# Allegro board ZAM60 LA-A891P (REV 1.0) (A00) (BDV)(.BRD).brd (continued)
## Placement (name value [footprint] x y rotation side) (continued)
LA6  BLM15PX330SN1D_2P  [MURAT_BLM15PX330SN1D_2P]  23.09 7.09 180 bottom
LA7  BLM15PX330SN1D_2P  [MURAT_BLM15PX330SN1D_2P]  23.09 8.8 180 bottom
LA8  BLM15PX330SN1D_2P  [MURAT_BLM15PX330SN1D_2P]  23.09 10.01 180 bottom
LA9  BLM15PX330SN1D_2P  [MURAT_BLM15PX330SN1D_2P]  23.09 11.72 180 bottom
LA10  BLM15PX330SN1D_2P  [MURAT_BLM15PX330SN1D_2P]  27.65 18.57 270 top
LA11  BLM15PX330SN1D_2P  [MURAT_BLM15PX330SN1D_2P]  24.2 18.62 270 top
LC1  2.2UH_LQM2MPN2R2NG0L_30%  [MURAT_LQM2MPN2R2NG0L_2P]  160.72 81.48 270 top
LC2  2.2UH_LQM2MPN2R2NG0L_30%  [MURAT_LQM2MPN2R2NG0L_2P]  163.07 81.48 270 top
LC3  2.2UH_LQM2MPN2R2NG0L_30%  [MURAT_LQM2MPN2R2NG0L_2P]  173.76 82.79 180 bottom
LC4  2.2UH_LQM2MPN2R2NG0L_30%  [MURAT_LQM2MPN2R2NG0L_2P]  142.75 81.28 90 bottom
LC5  2.2UH_LQM2MPN2R2NG0L_30%  [MURAT_LQM2MPN2R2NG0L_2P]  145.03 81.28 90 bottom
LED3  LTW-193ZDS5_WHITE  [LED_LTW-193ZDS5_2P]  295.45 87.55 0 top
LI1  DLW21HN900HQ2L_4P  [MURAT_DLW21HN900HQ2L_4P]  86 89 90 top
LI2  DLW21HN900HQ2L_4P  [MURAT_DLW21HN900HQ2L_4P]  87.6 88.99 90 top
LI3  DLW21HN900HQ2L_4P  [MURAT_DLW21HN900HQ2L_4P]  83.28 92.39 180 top
LI4  DLW21HN900HQ2L_4P  [MURAT_DLW21HN900HQ2L_4P]  242.97 86.69 90 bottom
LI5  DLW21HN900HQ2L_4P  [MURAT_DLW21HN900HQ2L_4P]  281.65 59.14 0 bottom
LI6  DLW21HN900HQ2L_4P  [MURAT_DLW21HN900HQ2L_4P]  281.65 60.8 0 bottom
LI7  DLW21HN900HQ2L_4P  [MURAT_DLW21HN900HQ2L_4P]  279.49 56.29 0 bottom
LI8  DLW21HN900HQ2L_4P  [MURAT_DLW21HN900HQ2L_4P]  239.78 88.54 90 bottom
LI9  DLW21HN900HQ2L_4P  [MURAT_DLW21HN900HQ2L_4P]  238.13 88.54 90 bottom
LL1  4.7UH_BRC2012T4R7MD_20%  [TAIYO_BRC2012T4R7MD_2P]  250.95 85.99 270 bottom
LV1  BLM15BB221SN1D_2P~D  [MURAT_BLM15BB221SN1D_2P]  115.25 86.96 270 top
LV3  DLW21HN900HQ2L_4P  [MURAT_DLW21HN900HQ2L_4P]  210.95 93.52 90 bottom
LV6  DLW21HN900HQ2L_4P  [MURAT_DLW21HN900HQ2L_4P]  208.85 93.52 90 bottom
LV10  DLW21HN900HQ2L_4P  [MURAT_DLW21HN900HQ2L_4P]  206.76 93.52 90 bottom
LV12  DLW21HN900HQ2L_4P  [MURAT_DLW21HN900HQ2L_4P]  213.05 93.52 90 bottom
LV22  BLM15PX181SN1D_2P  [MURAT_BLM15PX181SN1D_2P]  207.62 69.45 180 bottom
LV23  BLM15PX181SN1D_2P  [MURAT_BLM15PX181SN1D_2P]  209.61 70.72 90 bottom
LV24  BLM15PX181SN1D_2P  [MURAT_BLM15PX181SN1D_2P]  213.85 80.25 180 bottom
LV25  BLM15PX181SN1D_2P  [MURAT_BLM15PX181SN1D_2P]  213.1 75.93 0 bottom
LV27  DLW21HN900HQ2L_4P  [MURAT_DLW21HN900HQ2L_4P]  96.12 95.57 270 bottom
LZ1  DLW21HN900HQ2L_4P  [MURAT_DLW21HN900HQ2L_4P]  107.69 81.27 180 bottom
MIC1  SPM1437HM4H-6_6P  [KNOW_SPM1437HM4H-6_6P]  228.81 99.88 0 top
NOREF  -  []  169.65 73.51 0 top
NOREF#2  -  []  236.8 8.1 180 top
NOREF#3  -  []  135.19 -34.6 0 top
NOREF#4  -  []  88.07 31.21 0 top
NOREF#5  -  []  166.94 24.23 0 top
NOREF#6  -  []  56.7 105.85 270 top
NOREF#7  -  []  207.77 12.8 0 top
NOREF#8  -  []  69.98 61.55 90 top
NOREF#9  -  []  230.2 105.85 0 top
NOREF#10  -  []  92.2 88.9 0 top
NOREF#11  -  []  118.23 38.84 0 top
NOREF#12  -  []  277.87 63.56 0 top
NOREF#13  -  []  118.7 105.85 0 top
NOREF#14  -  []  299.7 11.15 270 top
NOREF#15  -  []  135.67 82 0 top
NOREF#16  -  []  266.87 24.6 0 top
NOREF#17  -  []  291.3 90.65 0 top
NOREF#18  -  []  163.57 33.84 0 top
NOREF#19  -  []  119.11 148.18 0 top
NOREF#20  -  []  283.7 49.65 270 top
NOREF#21  -  []  151.7 15.65 0 top
NOREF#22  -  []  184.7 105.85 0 top
NOREF#23  -  []  240.35 43.65 270 top
NOREF#24  -  []  274.91 67.86 180 bottom
NOREF#25  -  []  274.39 60.17 180 bottom
NOREF#26  -  []  258.95 72.21 180 bottom
NOREF#27  -  []  169.85 18.78 180 bottom
NOREF#28  -  []  193.94 28.42 180 bottom
PBATT1  DEREN_40-42251-01001RHF  [DEREN_40-42251-01001RHF_10P-T]  60.7 16.65 180 bottom
PC1  1U_0603_10V4Z  [C_0603]  291.96 7.03 270 top
PC3  2200P_0402_50V7K  [C_0402]  63.24 12.39 0 top
PC4  1500P_0402_50V7K  [C_0402]  48.31 11.79 0 top
PC5  0.022U_0805_50V7K  [C_0805]  63.18 103.76 270 top
PC9  1000P_0603_50V7K  [C_0603]  62.16 105.94 90 bottom
PC10  10U_0805_25V6K  [C_0805]  63.23 91.48 270 bottom
PC20  0.1U_0402_25V6  [C_0402]  74.28 101.36 270 top
PC21  10U_0805_25V6K  [C_0805]  59.32 101.52 0 top
PC22  10U_0805_25V6K  [C_0805]  63.64 105.93 90 bottom
PC100  4.7U_0603_10V6K  [C_0603]  218.3 48.37 270 bottom
PC101  10U_0805_25V6K  [C_0805]  218.23 57.86 270 bottom
PC102  10U_0805_25V6K  [C_0805]  217.79 57.86 270 top
PC105  2200P_0402_50V7K  [C_0402]  219.58 57.52 270 top
PC106  0.1U_0402_25V6  [C_0402]  219.58 57.51 270 bottom
PC109  0.1U_0603_25V7K  [C_0603]  221.98 49.32 0 top
PC110  0.1U_0603_25V7K  [C_0603]  213.34 49.32 0 top
PC111  680P_0603_50V7K  [C_0603]  227.01 57.63 90 top
PC113  220U_6.3V_M  [C_APXK6R3ARA221MF451]  228.53 49.51 180 bottom
PC114  680P_0603_50V7K  [C_0603]  210.17 55.04 270 top
PC115  220U_6.3V_M  [C_APXK6R3ARA221MF451]  207.72 49.57 0 bottom
PC117  0.1U_0603_25V7K  [C_0603]  219.44 51.42 90 bottom
PC118  4.7U_0603_10V6K  [C_0603]  218.17 51.42 90 bottom
PC119  1U_0603_10V6K  [C_0603]  214.87 47.1 180 top
PC200  10U_0805_25V6K  [C_0805]  63.18 23.68 270 top
PC201  10U_0805_25V6K  [C_0805]  64.89 23.68 270 top
PC203  2200P_0402_50V7K  [C_0402]  62.1 22.85 270 bottom
PC204  0.22U_0603_16V7K  [C_0603]  65.97 15.66 270 bottom
PC205  22U_0805_6.3V6M  [C_0805]  70.63 12.11 0 bottom
PC206  0.1U_0402_25V6  [C_0402]  61.2 22.85 270 bottom
PC207  220U_D2_2VY_R17M  [C_D2]  70.89 26.52 180 bottom
PC208  680P_0603_50V7K  [C_0603]  63.56 16.61 90 top
PC209  1U_0603_10V6K  [C_0603]  64.07 11.09 270 top
PC211  1U_0603_10V6K  [C_0603]  65.53 7.28 0 top
PC212  0.033U_0402_16V7K  [C_0402]  71.03 10.71 0 bottom
PC213  100P_0402_50V8J  [C_0402]  71.04 8.03 90 bottom
PC214  .1U_0402_16V7K  [C_0402]  71.03 9.82 0 bottom
PC215  .1U_0402_16V7K  [C_0402]  69.61 8.1 180 top
PC300  2200P_0402_50V7K  [C_0402]  201.67 63.8 180 bottom
PC301  680P_0603_50V7K  [C_0603]  201.72 58.66 180 top
PC302  0.1U_0603_25V7K  [C_0603]  205.15 62.59 180 top
PC303  10U_0805_25V6K  [C_0805]  200.76 61.68 270 bottom
PC304  330P_0402_50V7K  [C_0402]  207.62 59.54 180 bottom
PC305  47U_0805_6.3V6M  [C_0805]  204.3 50.72 0 top
PC306  47U_0805_6.3V6M  [C_0805]  204.3 52.43 0 top
PC307  22U_0805_6.3VAM  [C_0805]  201.11 50.72 180 top
PC308  22U_0805_6.3VAM  [C_0805]  201.11 52.43 180 top
PC309  4.7U_0603_6.3V6K  [C_0603]  206.68 62.85 0 bottom
PC310  4.7U_0603_6.3V6K  [C_0603]  204.33 63.93 0 bottom
PC311  0.1U_0402_25V6  [C_0402]  201.29 62.83 180 bottom
PC400  1U_0402_6.3V6K  [C_0402]  115.6 74.02 0 bottom
PC401  4.7U_0805_6.3V6K  [C_0805]  113.75 76.94 180 bottom
PC402  .1U_0402_16V7K  [C_0402]  116.53 72.16 270 bottom
PC403  0.01U_0402_25V7K  [C_0402]  106.28 74.1 270 bottom
PC404  22U_0805_6.3V6M  [C_0805]  109 76.94 0 bottom
PC500  4700P_0603_50V7K  [C_0603]  104.63 61.7 90 bottom
PC501  .1U_0402_16V7K  [C_0402]  105.71 63.05 270 bottom
PC502  0.068U_0402_16V7K  [C_0402]  108.7 66.03 270 top
PC503  1000P_0402_50V7K  [C_0402]  97.44 55.73 0 bottom
PC504  0.1U_0402_25V6  [C_0402]  97.7 58.15 0 bottom
PC505  1U_0603_10V6K  [C_0603]  98.74 69.76 0 top
PC506  100P_0402_50V8J  [C_0402]  109.53 69.77 180 top
PC507  0.33U_0603_10V7K  [C_0603]  106.54 72.56 270 top
PC508  680P_0603_50V7K  [C_0603]  102.28 50.08 90 bottom
PC509  1U_0603_10V7K  [C_0603]  105.39 56.94 90 bottom
PC510  1U_0603_10V7K  [C_0603]  105.27 72.56 270 top
PC511  0.1U_0402_25V6  [C_0402]  98.92 71.75 270 top
PC512  1500P_0402_50V7K  [C_0402]  108.63 72.45 270 top
PC513  0.068U_0402_16V7K  [C_0402]  109.58 66.03 270 top
PC514  47P_0402_50V8J  [C_0402]  102.07 72.61 0 top
PC515  10U_0805_25V6K  [C_0805]  99.35 52.17 0 top
PC516  10U_0805_25V6K  [C_0805]  99.35 52.17 0 bottom
PC517  10U_0805_25V6K  [C_0805]  99.35 50.39 0 bottom
PC518  10U_0805_25V6K  [C_0805]  99.35 50.39 0 top
PC519  100U_D_20VM_R55M  [C_D]  97.14 46.91 0 bottom
PC520  2200P_0402_50V7K  [C_0402]  99.74 53.57 0 top
PC521  0.1U_0402_25V6  [C_0402]  99.67 54.5 0 top
PC700  0.1U_0603_25V7K  [C_0603]  68.64 93.13 270 bottom
PC701  1U_0603_25V6K  [C_0603]  78.48 84.62 90 top
PC702  0.1U_0402_25V6  [C_0402]  79.27 88.77 180 bottom
PC703  0.1U_0402_25V6  [C_0402]  77.4 85.78 270 top
PC704  10U_0805_25V6K  [C_0805]  83.55 66.81 270 top
PC705  10U_0805_25V6K  [C_0805]  85.26 66.81 270 top
PC706  10U_0805_25V6K  [C_0805]  81.84 66.81 270 top
PC707  10U_0805_25V6K  [C_0805]  86.73 64.87 180 bottom
PC708  22U_0805_25V6M  [C_0805]  86.73 63.12 180 bottom
PC709  10U_0805_25V6K  [C_0805]  77.05 88.54 90 bottom
PC710  1U_0603_10V6K  [C_0603]  74.67 81.38 180 bottom
PC711  0.1U_0402_25V6  [C_0402]  79.56 85.78 270 top
PC712  0.047U_0603_25V7K~D  [C_0603]  73.2 83.87 0 bottom
PC713  2200P_0402_50V7K  [C_0402]  69.9 66.57 0 top
PC714  22U_0805_25V6M  [C_0805]  69.03 69.76 0 top
PC715  22U_0805_25V6M  [C_0805]  69.02 69.76 0 bottom
PC716  22U_0805_25V6M  [C_0805]  68.97 68.01 0 top
PC717  22U_0805_25V6M  [C_0805]  69.05 68.02 0 bottom
PC718  100P_0402_50V8J  [C_0402]  81.34 84.86 90 top
PC719  100P_0402_50V8J  [C_0402]  82.23 84.29 90 top
PC721  1000P_0603_50V7K  [C_0603]  74.06 78.29 270 top
PC722  0.1U_0603_25V7K  [C_0603]  90.28 63.74 270 top
PC723  10U_0805_25V6K  [C_0805]  88.57 63.89 270 top
PC724  10U_0805_25V6K  [C_0805]  90.28 63.89 270 bottom
PC725  10U_0805_25V6K  [C_0805]  88.57 63.89 270 bottom
PC726  0.1U_0402_25V6  [C_0402]  78.99 81.9 270 top
PC727  0.1U_0402_25V6  [C_0402]  78.98 80.11 0 top
PC728  0.1U_0402_25V6  [C_0402]  79.88 80.99 90 top
PC729  1U_0603_25V6K  [C_0603]  81.91 80.94 90 top
PC732  0.1U_0402_25V6  [C_0402]  69.31 66.62 0 bottom
PC737  100P_0402_50V8J  [C_0402]  84.07 81.05 90 bottom
PC741  100P_0402_50V8J  [C_0402]  84.07 79.21 90 bottom
PC805  0.1U_0402_10V7K  [C_0402]  66.46 32.81 0 top
PC807  0.47U_0805_25V6K  [C_0805]  116.61 100.82 0 top
PC809  1500P_0402_50V7K  [C_0402]  63.57 39.47 180 bottom
PC810  0.1U_0402_10V7K  [C_0402]  44.43 17.56 90 top
PC813  0.1U_0603_50V4Z  [C_0603]  80.88 39.73 90 top
PC815  0.1U_0603_25V7K  [C_0603]  79.61 39.73 90 top
PC816  0.047U_0603_25V7M  [C_0603]  73.9 36.75 180 top
PC817  0.1U_0402_25V4Z~D  [C_0402]  73.91 35.67 180 top
PC900  22U_0805_6.3V6M  [C_0805]  123.55 57.86 90 bottom
PC901  22U_0805_6.3V6M  [C_0805]  124.58 64.4 90 bottom
PC902  22U_0805_6.3V6M  [C_0805]  123.62 67.49 90 bottom
PC903  22U_0805_6.3V6M  [C_0805]  124.58 60.92 90 bottom
PC904  22U_0805_6.3V6M  [C_0805]  121.74 60.92 90 bottom
PC913  22U_0805_6.3V6M  [C_0805]  120.71 57.77 90 bottom
PC914  22U_0805_6.3V6M  [C_0805]  121.74 64.32 90 bottom
PC915  2.2U_0805_10V6K  [C_0805]  120.77 67.49 90 bottom
PC916  2.2U_0805_10V6K  [C_0805]  118.95 64.29 90 bottom
PC917  22U_0805_6.3V6M  [C_0805]  118.95 60.87 90 bottom
PC966  220U 2.5V Y D2 ESR9M H1.9 SX  [C_D2]  115.19 57.19 180 bottom
PD1  -  [TVNST52302AB0_SOT523-3]  54.8 10.26 180 top
PD2  -  [TVNST52302AB0_SOT523-3]  52.7 10.26 180 top
PD3  BAS40CW SOT-323  [BAS40-05W_SC70-3]  292.62 8.05 90 top
PD4  SDMK0340L-7-F_SOD323-2~D  [RB751V-40_SOD323-2]  50.73 9.36 270 top
PD5  -  [AZC199-02SPR7G_SOT23-3]  64.08 106.49 90 top
PD702  SDMK0340L-7-F_SOD323-2~D  [SDMK0340L-7-F_SOD323-2]  75.05 85.51 180 top
PD704  SDMK0340L-7-F_SOD323-2~D  [SDMK0340L-7-F_SOD323-2]  75.04 87.24 180 top
PD705  SDMK0340L-7-F_SOD323-2~D  [SDMK0340L-7-F_SOD323-2]  75.05 88.94 180 top
PD800  -  [PDS5100H-13_POWERDI5-3]  90.47 67.23 0 bottom
PD808  -  [PDS5100H-13_POWERDI5-3]  118.68 97.52 0 top
PD813  SDMK0340L-7-F_SOD323-2~D  [SDMK0340L-7-F_SOD323-2]  62.72 32.88 270 bottom
PD815  -  [BAT54CW_SOT323-3]  66.72 29.04 0 top
PD817  -  [BAT54CW_SOT323-3]  60.67 30.85 0 bottom
PH500  100K_0402_1%_NCP15WF104F03RC  [R_0402]  100.49 58.97 0 bottom
PH501  10K_0402_1%_TSM0A103F34D1RZ  [R_0402]  110.74 52.12 0 top
PJP1  PAD-OPEN 1x3m  [JUMP_43X118]  53.43 92.71 180 top
PJP4  PAD-OPEN1x1m  [JUMP_43X39]  272.98 13.89 180 bottom
PJP5  PAD-OPEN1x1m  [JUMP_43X39]  273.36 11.67 180 bottom
PJP6  PAD-OPEN1x2m  [JUMP_43X79]  30.23 16.56 0 bottom
PJP7  PAD-OPEN1x1m  [JUMP_43X39]  253.65 17.73 0 top
PJP9  PAD-OPEN1X2m  [JUMP_43X79]  39.84 9.13 180 top
PJP10  PAD-OPEN1x1m  [JUMP_43X39]  44.14 10.2 180 top
PJP11  PAD-OPEN1x1m  [JUMP_43X39]  189.6 79.67 0 top
PJP12  PAD-OPEN1x1m  [JUMP_43X39]  246.36 26.64 90 top
PJP13  PAD-OPEN1x2m  [JUMP_43X79]  239.65 60.96 90 top
PJP14  PAD-OPEN1x1m  [JUMP_43X39]  263.27 66.34 180 top
PJP15  PAD-OPEN1x1m  [JUMP_43X39]  269.87 39.03 180 top
PJP16  PAD-OPEN1x1m  [JUMP_43X39]  247.08 19.01 90 top
PJP17  PAD-OPEN1x1m  [JUMP_43X39]  244.26 33.13 0 top
PJP18  PAD-OPEN1x3m  [JUMP_43X118]  191.86 46.02 180 top
PJP20  PAD-OPEN1x1m  [JUMP_43X39]  227.19 64.07 270 top
PJP21  PAD-OPEN1x3m  [JUMP_43X118]  221.55 38.1 90 top
PJP22  PAD-OPEN1x3m  [JUMP_43X118]  214.75 34.43 270 top
PJP23  PAD-OPEN1x1m  [JUMP_43X39]  157.54 58.64 90 top
PJP24  PAD-OPEN1x1m  [JUMP_43X39]  216.66 73.15 270 bottom
PJP25  PAD-OPEN1x1m  [JUMP_43X39]  216.71 78.01 90 bottom
PJP26  PAD-OPEN1x2m  [JUMP_43X79]  277.88 24.87 0 top
PJP27  PAD-OPEN1x1m  [JUMP_43X39]  218.93 78.01 90 bottom
PJP28  PAD-OPEN1x1m  [JUMP_43X39]  218.88 72.24 90 bottom
PJP29  PAD-OPEN1x1m  [JUMP_43X39]  115.17 89.19 0 top
PJP32  PAD-OPEN1x1m  [JUMP_43X39]  240.2 54.58 90 top
PJP35  PAD-OPEN1x1m  [JUMP_43X39]  165.61 80.92 270 top
PJP36  PAD-OPEN1x3m  [JUMP_43X118]  169.45 82.12 270 top
PJP100  PAD-OPEN 1x3m  [JUMP_43X118]  214.76 62.91 0 bottom
PJP101  PAD-OPEN 1x3m  [JUMP_43X118]  208.26 45.36 270 top
PJP102  PAD-OPEN 1x3m  [JUMP_43X118]  227.72 49.7 0 top
PJP200  PAD-OPEN 1x2m~D  [JUMP_43X79]  60.09 23.41 0 top
PJP201  PAD-OPEN1x1m  [JUMP_43X39]  72.07 15.9 90 top
PJP202  PAD-OPEN1x1m  [JUMP_43X39]  70.98 14.07 0 bottom
PJP203  JUMP_1x3m  [JUMP_43X118]  84.41 28.17 0 top
PJP204  JUMP_1x3m  [JUMP_43X118]  84.41 22.96 0 top
PJP300  -  [JUMP_43X118]  202.8 48.98 270 bottom
PJP302  PAD-OPEN 1x2m~D  [JUMP_43X79]  208.89 65.38 180 bottom
PJP400  PAD-OPEN1x1m  [JUMP_43X39]  115.95 77.07 180 bottom
PJP401  PAD-OPEN1x1m  [JUMP_43X39]  107.69 77.01 180 bottom
PJP500  PAD-OPEN 4x4m  [JUMP_43X118-NPM]  94.76 51.92 0 bottom
PJP700  PAD-OPEN 4x4m  [JUMP_43X118-NPM]  69.04 78.81 315 bottom
PJP701  PAD-OPEN1x1m  [JUMP_43X39]  76.51 81.2 270 top
PJPDC1  ACES_50290-0050N-001  [ACES_50290-0050N-001_5P-T]  56.66 92.65 90 bottom
PL1  FBMJ4516HS720NT_2P  [TAIYO_FBMJ4516HS720NT_2P]  61.03 8.67 180 top
PL2  FBMJ4516HS720NT_2P  [TAIYO_FBMJ4516HS720NT_2P]  61.03 11.34 180 top
PL3  BLM15AG102SN1D_2P  [MURAT_BLM15AG102SN1D_2P]  61.3 104.01 270 top
PL4  FBMJ4516HS720NT_2P  [TAIYO_FBMJ4516HS720NT_2P]  63.11 103.34 0 bottom
PL100  1UH +-20% 6.6A  [L_5X5X3_M_2P-NPM]  213.26 62.91 0 bottom
PL101  2.2UH_7.8A_20%  [PANAS_ETQP3W2R2WFN_2P]  228.37 56.62 0 bottom
PL102  3.3UH_6.3A_20%  [PANAS_ETQP3W2R2WFN_2P]  215.04 56.62 0 bottom
PL200  1UH_11A_20%  [PANAS_ETQP3W2R2WFN_2P]  70.99 20.55 0 bottom
PL301  0.68UH +-20% 7.9A  [L_5X5X3_M_2P]  203.06 57.2 270 bottom
PL500  0.15UH_PCME064T-R15MS0R667_36A_20%  [PANAS_ETQP4LR15AFM_4P]  115.48 50.34 180 bottom
PL501  FBMA-L11-453215800LMA90T_2P  [KC_FBMA-L11-453215800LMA90T_2P]  93.41 51.92 0 bottom
PL700  1UH +-20% 6.6A  [L_5X5X3_M_2P]  71.07 76.93 135 bottom
PL701  3.3UH_10A_20%  [TOKO_FDVE1040-H-3R3M-P3_2P]  83.75 71.42 180 bottom
PQ1  DMG2301U-7 1P SOT23-3  [SI2301CDS-T1-GE3_SOT23-3]  47.75 7.89 0 top
PQ2  -  [FDV301N-G_SOT23-3]  70.04 104.47 0 top
PQ3  MMST3904-7-F_SOT323~D  [MMST3904-7-F_SOT323-3]  71.43 101.96 90 top
PQ4  -  [FDMC6679AZ_MLP8-5]  65.09 94.87 270 bottom
PQ6  DCX124EK-7-F PNP/NPN_SC74-6~D  [IMD2AT-108_SC74-6]  67.1 101.76 0 top
PQ100  -  [SIS412DN-T1-GE3_POWERPAK8-5]  223.8 57.67 90 top
PQ101  -  [SIS412DN-T1-GE3_POWERPAK8-5]  213.11 59.65 270 top
PQ102  -  [SI7716ADN-T1-GE3_POWERPAK8-5]  222.44 55.84 270 top
PQ103  -  [SI7716ADN-T1-GE3_POWERPAK8-5]  215.94 54 90 top
PQ200  -  [SIS412DN-T1-GE3_POWERPAK8-5]  66.7 22.03 0 top
PQ201  -  [SI7716ADN-T1-GE3_POWERPAK8-5]  64.92 20.46 270 top
PQ700  -  [SI4835DDY-T1-GE3_SO8]  63.66 96.05 90 top
PQ701  -  [NTR4502PT1G_SOT23-3]  68.17 92.68 270 top
PQ702  -  [NTR4502PT1G_SOT23-3]  68.17 96.68 270 top
PQ703  SI3993CDV-T1-GE3_TSOP6  [NTGD4161PT1G_TSOP6]  72.39 94.18 0 top
PQ705  -  [AON6970_DFN5X6D-8-7]  68.13 75.32 270 top
PQ800  -  [SI4835DDY-T1-GE3_SO8]  87.6 70.28 90 bottom
PQ806  -  [DMN65D8LDW-7_SOT363-6]  70.04 34.55 180 bottom
PQ810  -  [FDS6679AZ-G_SO8]  116.57 100.13 0 bottom
PQ813  -  [DMN65D8LDW-7_SOT363-6]  52.78 29.88 90 bottom
PQ814  -  [NTR4502PT1G_SOT23-3]  59.78 28.87 270 bottom
PQ815  -  [FDS6679AZ-G_SO8]  94.83 76.68 0 bottom
PQ816  -  [DMN65D8LW-7_SOT323-3]  59.34 33.84 90 bottom
PQ817  -  [DMN65D8LDW-7_SOT363-6]  47.2 18.1 0 top
PQ826  -  [FDMC6679AZ_MLP8-5]  95.68 78.7 90 bottom
PQ829  DMG2301U-7 1P SOT23-3  [SI2301CDS-T1-GE3_SOT23-3]  55.1 28.53 0 top
PQ832  -  [DMN65D8LW-7_SOT323-3]  66.15 30.91 90 top
PR1  1K_0402_5%  [R_0402]  296.43 7.66 180 top
PR2  100K_0402_5%  [R_0402]  50.21 10.71 0 top
PR6  0_0402_5%  [R0402_0OHM]  46.39 11.79 0 top
PR7  0_0402_5%  [R_0402]  72.37 100.44 90 bottom
PR8  2.2K_0402_5%  [R_0402]  73.33 103.19 270 bottom
PR9  33_0402_5%  [R_0402]  72.37 102.28 90 bottom
PR10  100K_0402_1%  [R_0402]  72.39 98.6 90 bottom
PR11  10K_0402_1%  [R_0402]  73.48 103.73 180 top
PR12  15K_0402_1%  [R_0402]  73.34 99.51 270 bottom
PR13  10K_0402_5%  [R_0402]  72.57 102.78 0 top
PR14  1M_0402_5%  [R_0402]  66.85 105.03 90 bottom
PR15  100K_0402_5%  [R_0402]  64.54 91.21 270 bottom
PR16  4.7K_0805_5%  [R_0805]  65.38 105.83 90 bottom
PR17  10K_0402_5%  [R_0402]  66.67 106.84 0 bottom
PR18  1M_0402_5%  [R_0402]  66.67 107.79 0 bottom
PR100  6.49K_0402_1%  [R_0402]  219.01 45.62 90 top
PR101  15K_0402_1%  [R_0402]  217.6 46.41 270 top
PR102  10K_0402_1%  [R_0402]  219.9 45.62 90 top
PR103  0_0402_5%  [R0402_0OHM]  219.06 44.93 90 bottom
PR104  10K_0402_1%  [R_0402]  216.71 46.41 270 top
PR105  20K_0402_1%  [R_0402]  220.79 45.62 90 top
PR106  16.9K_0402_1%  [R_0402]  215.82 45.5 90 top
PR107  100K_0402_1%  [R_0402]  222.61 47.94 270 top
PR108  0_0402_5%  [R0402_0OHM]  221.66 47.02 90 top
PR109  2.2_0603_5%  [R_0603]  214.74 50.59 180 top
PR110  2.2_0603_5%  [R_0603]  223.38 50.59 180 top
PR111  4.7_1206_5%  [R_1206]  227.2 53.76 90 top
PR112  4.7_1206_5%  [R_1206]  210.17 58.97 270 top
PR113  0_0402_5%  [R0402_0OHM]  213.59 46.02 0 top
PR114  200_0402_1%  [R_0402]  214.94 48.18 180 top
PR200  2.2_0603_5%  [R_0603]  67.24 15.66 270 bottom
PR201  19.6K_0402_1%  [R_0402]  65.66 9.61 90 top
PR202  5.1_0603_5%  [R_0603]  64.07 8.48 0 top
PR203  4.7_1206_5%  [R_1206]  67.56 16.61 180 top
PR204  0_0603_5%  [R0603_0OHM]  62.85 9.28 270 top
PR205  8.06K_0402_1%  [R_0402]  71.93 8.03 90 bottom
PR206  768K_0402_1%  [R_0402]  65.77 7.4 0 bottom
PR207  0_0402_5%  [R0402_0OHM]  68.68 7.23 0 top
PR209  10K_0402_1%  [R_0402]  71.03 7.16 0 bottom
PR210  0_0402_5%  [R0402_0OHM]  71.51 8.99 180 top
PR303  1M_0402_1%  [R_0402]  206.7 59.12 0 top
PR305  4.7_1206_5%  [R_1206]  203.95 57 180 top
PR306  0_0402_5%  [R_0402]  207.58 63.47 180 top
PR307  7.5K_0402_1%  [R_0402]  207.58 60.88 180 bottom
PR308  0_0402_5%  [R_0402]  206.66 62.58 0 top
PR309  1K_0402_5%  [R_0402]  205.31 59.6 90 top
PR310  10K_0402_1%  [R_0402]  206.66 61.77 0 bottom
PR312  0_0603_5%  [R0603_0OHM]  203.76 61.39 270 top
PR313  0_0402_5%  [R0402_0OHM]  207.58 60.78 180 top
PR315  100K_0402_1%  [R_0402]  207.58 61.7 180 top
PR400  100K_0402_5%  [R_0402]  116.52 73.07 180 bottom
PR401  47K_0402_5%  [R_0402]  115.62 72.17 270 bottom
PR402  8.66K_0402_1%  [R_0402]  107.17 74.1 270 bottom
PR403  10K_0402_1%  [R_0402]  107.17 72.26 270 bottom
PR500  75_0402_1%  [R_0402]  106.6 63.05 270 bottom
PR501  365K_0402_1%  [R_0402]  103.49 63.11 270 bottom
PR502  75_0402_1%  [R_0402]  102.6 63.11 270 bottom
PR503  681K_0402_1%  [R_0402]  101.71 63.11 270 bottom
PR504  36.5K_0402_1%  [R_0402]  100.82 63.11 270 bottom
PR505  10K_0402_5%  [R_0402]  105.52 65.84 270 bottom
PR506  39K_0402_1%  [R_0402]  104.63 65.84 270 bottom
PR507  150K_0402_1%  [R_0402]  103.74 65.84 270 bottom
PR508  100K_0402_1%  [R_0402]  102.85 65.84 270 bottom
PR509  20K_0402_1%  [R_0402]  101.96 65.84 270 bottom
PR510  39K_0402_5%~N  [R_0402]  106.41 65.84 270 bottom
PR511  10K_0402_5%  [R_0402]  107.49 62.14 90 bottom
PR512  2.15K_0402_1%  [R_0402]  110.3 51.24 270 top
PR513  75_0402_1%  [R_0402]  100.14 65.7 180 top
PR514  20K_0402_1%  [R_0402]  111.19 51.24 270 top
PR515  3.01K_0402_1%  [R_0402]  112.07 51.24 270 top
PR516  1.91K_0402_1%  [R_0402]  100.14 67.48 180 top
PR517  2.2_0603_5%  [R_0603]  98.6 57.07 180 bottom
PR518  2M_0402_1%  [R_0402]  96.7 61.04 90 top
PR519  1_0603_5%  [R_0603]  98.74 68.55 0 top
PR520  0_0402_5%  [R0402_0OHM]  99.22 64.82 0 top
PR521  4.87K_0402_1%  [R_0402]  107.68 71.69 270 top
PR522  4.7_1206_5%  [R_1206]  103.93 52.75 270 bottom
PR523  10K_0402_5%  [R_0402]  109.53 70.66 180 top
PR524  2M_0402_1%  [R_0402]  97.74 62.93 0 top
PR525  27K_0402_1%  [R_0402]  97.66 62 270 top
PR526  10_0603_1%  [R_0603]  104 71.17 90 top
PR527  54.9_0402_1%  [R_0402]  102.03 71.75 270 top
PR528  75_0402_1%  [R_0402]  101.14 71.75 270 top
PR529  110_0402_1%  [R_0402]  99.81 71.75 270 top
PR531  0_0402_5%  [R0402_0OHM]  109.53 68.75 180 top
PR532  0_0402_5%  [R0402_0OHM]  109.53 67.86 180 top
PR534  0_0402_5%  [R0402_0OHM]  102.92 71.75 270 top
PR535  4.75K_0402_1%  [R_0402]  109.52 71.53 90 top
PR536  0_0402_5%  [R0402_0OHM]  99.22 63.93 0 top
PR539  0_0402_5%  [R0402_0OHM]  100.14 66.59 180 top
PR700  0_0402_5%  [R0402_0OHM]  65.28 99.53 0 top
PR701  0.01_1206_1%  [R_1206_4P-D]  66.8 88.34 90 bottom
PR702  0_0402_5%  [R0402_0OHM]  68.64 89.75 90 bottom
PR703  100_0402_1%  [R_0402]  78.36 91.43 0 bottom
PR704  0_0402_5%  [R0402_0OHM]  79.26 90.56 270 bottom
PR705  0_0402_5%  [R0402_0OHM]  78.37 90.56 270 bottom
PR706  100K_0402_1%  [R_0402]  73.34 91.72 90 top
PR707  100K_0402_1%  [R_0402]  72.39 91.72 90 top
PR708  10_1206_5%  [R_1206]  74.19 89.37 270 bottom
PR709  0_0402_5%  [R0402_0OHM]  74.29 91.72 90 top
PR710  34K_0402_1%  [R_0402]  80.58 87.36 180 top
PR711  6.49K_0402_1%  [R_0402]  80.45 85.78 270 top
PR712  2.2_0603_5%  [R_0603]  74.6 82.6 180 bottom
PR713  100K_0402_1%  [R_0402]  78 77.88 90 bottom
PR714  0_0402_5%  [R0402_0OHM]  80.12 88.45 270 bottom
PR715  154K_0402_1%  [R_0402]  78.1 80.92 90 top
PR716  0_0402_5%  [R0402_0OHM]  81.07 88.45 270 bottom
PR717  0_0402_5%  [R0402_0OHM]  84.47 83.29 180 bottom
PR718  0_0402_5%  [R0402_0OHM]  84.47 85.06 180 bottom
PR720  0_0402_5%  [R0402_0OHM]  84.47 84.18 180 bottom
PR721  0.01_1206_1%  [R_1206_4P-D]  87.02 69.2 180 top
PR722  4.02K_0402_1%  [R_0402]  80.08 78.76 270 bottom
PR723  10_0603_1%  [R_0603]  81.59 79.35 270 bottom
PR725  1K_0402_5%  [R_0402]  78.89 77.88 90 bottom
PR726  4.7_1206_5%  [R_1206]  72.73 77.3 180 top
PR728  0_0402_5%  [R0402_0OHM]  83.06 78.45 90 bottom
PR729  154K_0402_1%  [R_0402]  80.77 80.99 90 top
PR737  649K_0402_1%  [R_0402]  85.85 80.16 90 bottom
PR738  3M_0402_5%  [R_0402]  84.96 81.08 270 bottom
PR740  10K_0402_1%  [R_0402]  84.95 79.29 0 bottom
PR743  0_0402_5%  [R0402_0OHM]  84.95 78.4 0 bottom
PR745  100K_0402_1%  [R_0402]  83.18 81.05 90 bottom
PR788  20K_0402_1%  [R_0402]  81.96 83.34 0 top
PR799  10K_0402_1%  [R_0402]  77.12 78.79 270 bottom
PR810  100K_0402_5%  [R_0402]  68.75 32.23 90 bottom
PR811  0_0402_5%  [R0402_0OHM]  121.51 100.44 0 top
PR812  0_0402_5%  [R0402_0OHM]  70.67 37 180 top
PR813  100K_0402_5%  [R_0402]  94.73 72.61 90 top
PR814  330K_0402_5%  [R_0402]  122.22 92.23 90 top
PR815  100K_0402_5%  [R_0402]  95.68 72.61 90 top
PR816  0_0402_5%  [R_0402]  96.61 73.61 90 top
PR818  100K_0402_5%  [R_0402]  62.66 40.36 0 bottom
PR819  100K_0402_5%  [R_0402]  45.32 17.56 90 top
PR822  10K_0402_5%  [R_0402]  61.39 33.68 180 bottom
PR826  100K_0402_5%  [R_0402]  54.86 27.9 90 bottom
PR827  100K_0402_5%  [R_0402]  55.81 27.9 90 bottom
PR828  10K_0402_5%  [R_0402]  71.13 28.87 180 top
PR829  100K_0402_5%  [R_0402]  51.36 29.62 90 bottom
PR830  100K_0402_5%  [R_0402]  55.15 32.37 0 top
PR831  100_0603_1%  [R_0603]  83.75 36.75 270 top
PR832  100_0603_1%  [R_0603]  85.09 35.36 90 top
PR835  47_0805_5%~D  [R_0805]  83.78 39.53 180 top
PR838  100_0603_1%  [R_0603]  83.49 32.68 270 top
PR842  0_0402_5%  [R0402_0OHM]  78.53 40.57 270 top
PR843  0_0402_5%  [R0402_0OHM]  80.95 29.9 270 top
PR844  10K_0402_5%  [R_0402]  68.44 29.01 270 top
PR845  0_0402_5%  [R0402_0OHM]  80.06 29.9 270 top
PR846  100K_0402_5%  [R_0402]  77.65 41.69 0 top
PR847  100_0603_1%  [R_0603]  77.47 40.78 270 top
PR848  0_0402_5%  [R0402_0OHM]  79.17 29.9 270 top
PR850  0_0402_5%  [R0402_0OHM]  78.28 29.9 270 top
PR851  0_0402_5%  [R0402_0OHM]  76.34 40.45 270 top
PR853  0_0402_5%  [R0402_0OHM]  55.93 31.43 270 bottom
PR854  0_0402_5%  [R0402_0OHM]  75.56 29.38 180 top
PR855  0_0402_5%  [R0402_0OHM]  75.4 40.45 270 top
PR857  0_0402_5%  [R0402_0OHM]  73.91 32.62 180 top
PR858  1M_0402_5%  [R_0402]  77.39 28.99 90 top
PR859  0_0402_5%  [R0402_0OHM]  73.91 31.67 180 top
PR860  100_0603_1%  [R_0603]  73.91 34.59 180 top
PR863  0_0402_5%  [R_0402]  75.56 30.27 180 top
PR864  100K_0402_5%  [R_0402]  65.08 39.67 270 bottom
PR874  1M_0402_5%  [R_0402]  73.91 33.51 180 top
PR895  0_0402_5%  [R0402_0OHM]  56.07 33.26 180 top
PRP2  100_0804_8P4R_5%  [RP_0804_8P4R]  53.03 7.72 90 top
PT1  PAD~D  [TPC12]  86.17 82.65 0 top
PT2  PAD~D  [TPC12]  84.77 82.54 0 top
PU1  TS5A63157DCKR_SC70-6~D  [TS5A63157DCKR_SC70-6]  73.93 107.12 180 top
PU100  -  [TPS51285BRUKR_QFN20_3X3]  217.48 48.03 0 top
PU200  -  [RT8207MZQW_WQFN20_3X3]  69.16 11.39 270 bottom
PU300  SYX198DQNC_QFN10_3X3  [SY8208DQNC_QFN10_3X3]  205.3 60.01 90 bottom
PU400  -  [APL5930KAI-TRG_SO8]  108.84 71.29 90 bottom
PU500  TPS51624RSM_QFN32_4X4  [TPS51622RSM_QFN32_4X4]  102.51 68.43 270 top
PU501  -  [CSD97374CQ4M_SON8_3P5X4P5]  103.71 57.59 270 bottom
PU700  BQ24777RUYR_WQFN28_4x4  [BQ24715URUYR_WQFN28_4X4]  78.43 85.21 270 bottom
PU800  CD3301BRHHR_QFN36_6X6~D  [CD3301RHHR_QFN36_6X6]  80.85 37.62 180 top
PU804  TC7SH08FU_SSOP5~D  [TC7SH08FU_SSOP5]  70.67 35.86 180 top
PU806  TC7SH08FU_SSOP5~D  [TC7SH08FU_SSOP5]  47.21 21.45 0 top
QA1  -  [L2N7002WT1G_SC-70-3]  38.4 23.73 90 top
QA2  -  [DMN66D0LDW-7_SOT363-6]  27.23 27.05 270 top
QA3  -  [DMN66D0LDW-7_SOT363-6]  40.3 25.75 90 top
QC1  -  [DMN66D0LDW-7_SOT363-6]  192.59 51.27 90 top
QD1  -  [L2N7002WT1G_SC-70-3]  153.49 23.9 0 top
QE2  -  [DMN66D0LDW-7_SOT363-6]  251.44 46.89 90 top
QE3  MMBT3904WT1G_SC70-3~D  [MMBT3904WT1G_SC70-3]  148.35 63.02 270 top
QE4  MMBT3904WT1G_SC70-3~D  [MMBT3904WT1G_SC70-3]  251.52 35.85 180 top
QE5  MMBT3904WT1G_SC70-3~D  [MMBT3904WT1G_SC70-3]  152.13 21.44 270 bottom
QE6  MMBT3904WT1G_SC70-3~D  [MMBT3904WT1G_SC70-3]  101.54 46.46 270 top
QE7  MMBT3904WT1G_SC70-3~D  [MMBT3904WT1G_SC70-3]  235.42 37.85 270 bottom
QL1  -  [DMN66D0LDW-7_SOT363-6]  281.15 80.82 0 top
QL2  -  [DMN66D0LDW-7_SOT363-6]  282.45 79.67 180 top
QN1  -  [DMN66D0LDW-7_SOT363-6]  277.18 10.14 180 bottom
QV1  -  [AO6405_TSOP6]  109.82 85.38 270 top
QV2  -  [L2N7002WT1G_SC-70-3]  110.81 79.41 90 top
QV7  -  [L2N7002WT1G_SC-70-3]  97.28 87.73 0 top
QV8  -  [LP2301ALT1G_SOT23-3]  97.98 91.88 180 top
QV9  -  [L2N7002WT1G_SC-70-3]  204.99 91.44 270 top
QV10  -  [L2N7002WT1G_SC-70-3]  196.56 85.37 90 top
QV20  -  [SI3456DDV-T1-GE3_TSOP6]  199.17 68.74 270 bottom
QV21  -  [DMN66D0LDW-7_SOT363-6]  198.89 65.33 270 bottom
QV501  -  [L2N7002WT1G_SC-70-3]  288.16 69.31 0 top
QV502  -  [L2N7002WT1G_SC-70-3]  284.64 67.79 180 top
QZ1  -  [LP2301ALT1G_SOT23-3]  103.31 87.85 180 top
QZ2  -  [DMN66D0LDW-7_SOT363-6]  242.35 35.8 0 top
QZ3  -  [DMN66D0LDW-7_SOT363-6]  271.7 21.51 180 top
QZ4  -  [DDTA114EUA-7-F_SOT323-3]  276.53 20.78 90 top
QZ6  -  [SI3456DDV-T1-GE3_TSOP6]  166.03 85.9 180 top
QZ7  -  [DMN66D0LDW-7_SOT363-6]  288.59 81.12 90 top
QZ9  -  [DDTA114EUA-7-F_SOT323-3]  284.79 79.63 0 top
QZ10  -  [DMN66D0LDW-7_SOT363-6]  149.84 84.26 90 top
QZ11  -  [DMN66D0LDW-7_SOT363-6]  242.95 71.04 180 top
R6  10_0402_5%  [R_0402]  152.78 94.09 270 bottom
R41  10_0402_5%  [R_0402]  155.83 94.09 270 bottom
R252  33_0402_5%  [R_0402]  135.37 92.68 90 bottom
R253  33_0402_5%  [R_0402]  136.25 92.68 90 bottom
R254  33_0402_5%  [R_0402]  136.25 93.59 270 top
R255  33_0402_5%  [R_0402]  137.14 92.68 90 bottom
R256  33_0402_5%  [R_0402]  137.14 93.59 270 top
R257  33_0402_5%  [R_0402]  138.03 92.68 90 bottom
R258  33_0402_5%  [R_0402]  139.81 93.59 270 top
R259  33_0402_5%  [R_0402]  134.48 92.68 90 bottom
R260  33_0402_5%  [R_0402]  134.48 93.59 270 top
R261  33_0402_5%  [R_0402]  135.37 93.59 270 top
R262  33_0402_5%  [R_0402]  138.03 93.59 270 top
R263  33_0402_5%  [R_0402]  138.92 92.68 90 bottom
R264  33_0402_5%  [R_0402]  138.92 93.59 270 top
R265  33_0402_5%  [R_0402]  139.81 92.68 90 bottom
R266  33_0402_5%  [R_0402]  140.7 92.68 90 bottom
R267  33_0402_5%  [R_0402]  140.7 93.59 270 top
R268  100K_0402_5%  [R_0402]  143.37 93.59 270 bottom
R271  100K_0402_5%  [R_0402]  142.43 104.57 180 top
R272  100K_0402_5%  [R_0402]  168.55 104.7 180 top
R273  10_0402_5%  [R_0402]  168.15 96.29 90 top
RA1  10K_0402_5%  [R_0402]  20.67 15.02 180 bottom
RA2  100K_0402_5%  [R_0402]  20.65 17.91 270 bottom
RA3  0_0603_5%  [R0603_0OHM]  30.24 12.13 0 top
RA4  0_0603_5%  [R0603_0OHM]  27.43 8.74 90 top
RA5  2.2K_0402_5%  [R_0402]  27.65 19.62 180 top
RA6  2.2K_0402_5%  [R_0402]  24.44 19.62 0 top
RA7  24.9_0402_1%  [R_0402]  22.46 12.73 90 top
RA8  24.9_0402_1%  [R_0402]  22.87 16.48 180 top
RA9  33_0402_5%  [R_0402]  42.16 19.22 180 top
RA12  1K_0402_5%  [R_0402]  40.74 21.06 0 top
RA13  1K_0402_5%  [R_0402]  40.74 22.02 0 top
RA14  33_0402_5%  [R_0402]  38.9 13.95 0 top
RA17  33_0402_5%  [R_0402]  39.02 17.38 0 top
RA18  10K_0402_5%  [R_0402]  38.53 12.1 90 top
RA21  100K_0402_5%  [R_0402]  30.21 27.17 270 top
RA24  4.7K_0402_5%  [R_0402]  21.96 14.58 0 top
RA25  4.7K_0402_5%  [R_0402]  21.96 15.53 0 top
RA26  100K_0402_5%  [R_0402]  37.08 26.85 270 top
RA27  200K_0402_5%  [R_0402]  36.36 24.05 0 top
RA28  100K_0402_5%  [R_0402]  36.36 25 0 top
RA29  100K_0402_5%  [R_0402]  41.45 25.5 90 top
RA30  22_0402_5%  [R_0402]  35.43 24.12 270 top
RA31  22_0402_5%  [R_0402]  35.24 26.34 270 top
RA32  33_0402_5%  [R_0402]  34.48 24.12 270 top
RA35  0_0402_5%  [R0402_0OHM]  32.81 20.8 0 bottom
RA36  0_0402_5%  [R0402_0OHM]  27.1 12.5 0 bottom
RA37  0_0402_5%  [R0402_0OHM]  33.26 27.09 0 bottom
RA38  100K_0402_5%  [R_0402]  36.19 25.93 90 top
RA39  0_0805_5%  [R0805_0OHM]  37.03 8.94 180 top
RA40  33_0402_5%  [R_0402]  39.4 13.06 0 top
RA44  100K_0402_5%  [R_0402]  30.83 23.39 90 bottom
RA45  0_0402_5%  [R0402_0OHM]  29.72 23.46 90 top
RC1  330K_0402_5%  [R_0402]  168.21 45.68 90 bottom
RC2  1K_0402_5%  [R_0402]  290.13 10.13 270 bottom
RC4  0_0402_5%  [R0402_0OHM]  181.61 48.31 270 bottom
RC7  10M_0402_5%  [R_0402]  181.61 46.34 270 bottom
RC8  20K_0402_5%  [R_0402]  187.77 45.83 270 bottom
RC9  1M_0402_5%  [R_0402]  170.49 45.68 90 bottom
RC10  20K_0402_5%  [R_0402]  188.72 45.83 270 bottom
RC11  1K_0402_5%  [R_0402]  168.03 45.38 180 top
RC14  51_0402_5%  [R_0402]  125.54 46.98 270 top
RC15  51_0402_5%  [R_0402]  128.39 46.98 270 top
RC16  51_0402_5%  [R_0402]  127.44 46.98 270 top
RC17  3.01K_0402_1%  [R_0402]  162.86 80.05 0 bottom
RC18  1K_0402_1%  [R_0402]  126.49 46.98 270 top
RC19  33_0402_5%  [R_0402]  154.97 40.49 0 bottom
RC20  33_0402_5%  [R_0402]  154.97 41.57 0 bottom
RC21  51_0402_5%  [R_0402]  127.48 58.4 0 bottom
RC22  33_0402_5%  [R_0402]  154.97 38.59 0 bottom
RC23  33_0402_5%  [R_0402]  154.97 39.54 0 bottom
RC25  1K_0402_5%  [R_0402]  128.97 82.73 270 bottom
RC26  0_0402_5%  [R0402_0OHM]  188.15 50.24 0 top
RC27  0_0402_5%  [R_0402]  184.35 52.23 0 top
RC29  1K_0402_5%  [R_0402]  188.34 65.2 270 top
RC31  1K_0402_5%  [R_0402]  188.72 59.48 180 top
RC33  499_0402_1%  [R_0402]  180.06 59.29 0 bottom
RC34  499_0402_1%  [R_0402]  180.06 58.4 0 bottom
RC35  0_0402_5%  [R0402_0OHM]  188.83 66.99 270 bottom
RC38  33_0402_5%  [R_0402]  188.85 64.1 90 bottom
RC50  0_0402_5%  [R0402_0OHM]  187.94 54.46 0 bottom
RC55  33_0402_5%  [R_0402]  187.94 53 0 bottom
RC61  33_0402_5%  [R_0402]  188.91 58.51 90 bottom
RC62  33_0402_5%  [R_0402]  196.02 59.78 90 bottom
RC63  1M_0402_5%  [R_0402]  155.44 81.01 180 bottom
RC65  0_0402_5%  [R0402_0OHM]  155.8 80.06 0 bottom
RC66  10K_0402_5%  [R_0402]  178.13 62.01 180 top
RC67  22_0402_5%  [R_0402]  164.12 42.99 0 top
RC68  10K_0402_5%  [R_0402]  175.12 65.91 270 bottom
RC69  3.01K_0402_1%  [R_0402]  152.59 80.03 90 bottom
RC70  22_0402_5%  [R_0402]  164.12 43.94 0 top
RC72  22_0402_5%  [R_0402]  160.45 42.9 0 top
RC74  22_0402_5%  [R_0402]  160.45 41.95 0 top
RC77  0_0402_5%  [R0402_0OHM]  186.36 72.77 270 top
RC78  330K_0402_5%  [R_0402]  169.54 46.6 270 bottom
RC79  10K_0402_5%  [R_0402]  171.07 45.36 90 top
RC80  8.2K_0402_5%  [R_0402]  184.72 74.28 180 top
RC81  10K_0402_5%  [R_0402]  178 60.17 270 top
RC82  10K_0402_5%  [R_0402]  177.11 60.17 270 top
RC87  0_0402_5%  [R0402_0OHM]  191.15 71.73 180 top
RC88  0_0402_5%  [R0402_0OHM]  190.89 73.82 180 top
RC89  0_0402_5%  [R0402_0OHM]  191.15 72.68 180 top
RC91  10K_0402_5%  [R_0402]  168.02 46.91 180 top
RC92  10K_0402_5%  [R_0402]  174.14 45.3 90 top
RC95  8.2K_0402_5%  [R_0402]  186.56 74.28 180 top
RC98  0_0402_5%  [R_0402]  93.53 58.08 180 bottom
RC99  0_0402_5%  [R_0402]  93.53 56.18 180 bottom
RC102  1K_0402_5%  [R_0402]  74.84 52.12 0 top
RC103  1K_0402_5%  [R_0402]  74.84 51.23 0 top
RC106  1K_0402_5%  [R_0402]  87.13 50.71 180 top
RC109  0_0402_5%  [R_0402]  86.79 57.78 270 bottom
RC112  0_0402_5%  [R_0402]  92.62 59.99 0 bottom
RC113  1K_0402_5%  [R_0402]  86.22 45.31 0 top
RC114  49.9_0402_1%  [R_0402]  127.75 69.38 0 bottom
RC115  0_0402_5%  [R_0402]  92.62 59.04 0 bottom
RC116  62_0402_5%  [R_0402]  125.87 69.32 180 bottom
RC117  51_0402_5%  [R_0402]  87.13 47.09 180 top
RC118  0_0402_5%  [R_0402]  92.62 57.13 0 bottom
RC119  0_0402_5%  [R_0402]  75.93 46.32 90 top
RC120  1K_0402_5%  [R_0402]  75.94 48.31 180 top
RC121  56_0402_5%  [R_0402]  124.95 70.27 0 bottom
RC122  1K_0402_5%  [R_0402]  87.12 48.69 180 top
RC123  10K_0402_5%  [R_0402]  132.59 78.07 90 bottom
RC124  51_0402_5%  [R_0402]  127.89 80.95 270 bottom
RC125  51_0402_5%  [R_0402]  127.89 82.19 90 bottom
RC126  51_0402_5%  [R_0402]  126.87 82.19 90 bottom
RC127  51_0402_5%  [R_0402]  126.87 80.95 270 bottom
RC128  51_0402_5%  [R_0402]  75.93 44.42 90 top
RC129  51_0402_5%  [R_0402]  86.79 59.68 270 bottom
RC130  200_0402_1%  [R_0402]  132.4 46.78 225 top
RC131  121_0402_1%  [R_0402]  130.68 46.98 270 top
RC132  100_0402_1%  [R_0402]  129.73 46.98 270 top
RC133  24.9_0402_1%  [R_0402]  158.44 68.55 180 top
RC136  0_0402_5%  [R_0402]  175.32 61.26 270 top
RC139  100K_0402_5%  [R_0402]  168.65 78.98 270 top
RC140  1K_0402_5%  [R_0402]  177.47 65.95 0 top
RC141  100K_0402_5%  [R_0402]  170.86 81.02 270 bottom
RC142  100K_0402_5%  [R_0402]  167.13 80.95 270 bottom
RC149  3.01K_0402_1%  [R_0402]  151.71 80.05 180 bottom
RC152  22.6_0402_1%  [R_0402]  163.89 46.98 270 top
RC153  10K_0402_5%  [R_0402]  175.05 46.22 270 top
RC155  100K_0402_5%  [R_0402]  177.21 63.22 0 bottom
RC156  100K_0402_5%  [R_0402]  175.97 65.95 180 top
RC158  100K_0402_5%  [R_0402]  175.21 68.81 180 bottom
RC160  100K_0402_5%  [R_0402]  175.21 67.92 180 bottom
RC161  0_0402_5%  [R0402_0OHM]  128.97 80.95 270 bottom
RC163  10K_0402_5%  [R_0402]  170.49 78.98 270 top
RC164  20K_0402_5%  [R_0402]  172.4 78.98 270 top
RC171  10K_0402_5%  [R_0402]  176.35 63.22 180 bottom
RC174  100K_0402_5%  [R_0402]  179.59 57.95 180 top
RC175  100K_0402_5%  [R_0402]  176.83 57.95 0 top
RC176  1K_0402_5%  [R_0402]  171.45 78.98 270 top
RC178  49.9_0402_1%  [R_0402]  164.21 46.98 270 bottom
RC179  1K_0402_5%  [R_0402]  178.13 61.12 180 top
RC180  1K_0402_5%  [R_0402]  178.13 62.9 180 top
RC183  1K_0402_1%  [R_0402]  128.39 60.88 180 bottom
RC184  1K_0402_1%  [R_0402]  128.39 61.77 180 bottom
RC185  49.9_0402_1%  [R_0402]  127.48 57.51 0 bottom
RC186  8.2K_0402_1%  [R_0402]  160.7 80.05 0 bottom
RC187  49.9_0402_1%  [R_0402]  163.32 46.98 270 bottom
RC188  1K_0402_1%  [R_0402]  128.39 62.66 180 bottom
RC189  1K_0402_1%  [R_0402]  128.39 64.43 180 bottom
RC190  1K_0402_1%  [R_0402]  128.39 63.55 180 bottom
RC191  1K_0402_5%  [R_0402]  122.25 45.82 180 top
RC192  0_0402_5%  [R_0402]  169.4 76.75 0 bottom
RC193  0_0402_5%  [R_0402]  130.68 77.65 270 bottom
RC194  0_0402_5%  [R_0402]  176.1 46.96 180 bottom
RC195  0_0402_5%  [R_0402]  129.65 46.96 0 bottom
RC196  0_0603_5%  [R_0603]  131.24 80.12 90 bottom
RC197  150_0402_5%  [R_0402]  126.87 79.04 270 top
RC198  10K_0402_5%  [R_0402]  127.82 78.13 90 top
RC199  10K_0402_5%  [R_0402]  129.92 82.73 270 bottom
RC201  1.5K_0402_5%  [R_0402]  129.92 80.95 270 bottom
RC202  1K_0402_5%  [R_0402]  142.75 80.06 270 top
RC204  75_0402_1%  [R_0402]  126.86 67.88 270 bottom
RC207  43_0402_5%  [R_0402]  127.76 66 90 bottom
RC208  110_0402_1%  [R_0402]  127.75 67.86 0 bottom
RC209  100_0402_1%  [R_0402]  128.84 77.08 270 bottom
RC211  5.11_0402_1%  [R_0402]  158.87 46.06 90 top
RC212  0_0402_5%  [R0402_0OHM]  172.02 45.36 90 top
RC213  0_0402_5%  [R_0402]  172.97 45.36 90 top
RC216  0_0402_5%  [R_0402]  174.1 43.22 0 top
RC217  0_0402_5%  [R0402_0OHM]  174.1 44.17 0 top
RC218  100_0402_1%  [R_0402]  128.85 75.16 180 bottom
RC219  0_0402_5%  [R0402_0OHM]  191.15 70.78 180 top
RC224  0_0402_5%  [R_0402]  179.75 81.02 270 top
RC225  0_0402_5%  [R_0402]  180.77 81.02 270 top
RC226  0_0402_5%  [R_0402]  181.78 81.02 270 top
RC227  0_0402_5%  [R_0402]  182.8 81.02 270 top
RC228  0_0402_5%  [R_0402]  183.82 81.02 270 top
RC229  0_0402_5%  [R_0402]  184.83 81.02 270 top
RC230  0_0402_5%  [R_0402]  185.85 81.02 270 top
RC231  0_0402_5%  [R_0402]  186.86 80.11 90 top
RC240  10K_0402_5%  [R_0402]  147.71 80.05 180 bottom
RC241  10K_0402_5%  [R_0402]  148.64 80.05 0 bottom
RC242  10K_0402_5%  [R_0402]  165.78 46.98 270 top
RC243  10K_0402_5%  [R_0402]  164.83 46.98 270 top
RC245  100K_0402_5%  [R_0402]  170.11 46.28 270 top
RC247  10K_0402_5%  [R_0402]  178.99 60.49 90 top
RC300  10K_0402_5%  [R_0402]  164.81 61.92 90 top
RC301  0_0402_5%  [R_0402]  259.27 22.67 90 top
RC302  1K_0402_5%  [R_0402]  183.87 64.63 0 top
RC303  1K_0402_5%  [R_0402]  184.78 63.72 270 top
RC304  100K_0402_5%  [R_0402]  190.31 74.88 180 top
RC305  1K_0402_5%  [R_0402]  87.59 41.43 180 top
RC306  10K_0402_5%  [R_0402]  169.56 78.07 90 top
RD2  470_0402_5%  [R_0402]  97.67 12.93 180 top
RD4  1.8K_0402_1%  [R_0402]  81.54 17.18 180 top
RD5  2_0402_1%  [R_0402]  79.56 16.31 270 top
RD6  1.8K_0402_1%  [R_0402]  78.62 16.93 180 top
RD7  24.9_0402_1%  [R_0402]  81.47 16.31 270 top
RD9  220K_0402_5%  [R_0402]  149.97 20.67 90 top
RD10  66.5_0402_1%  [R_0402]  118.68 10.4 180 top
RD11  66.5_0402_1%  [R_0402]  118.68 9.51 180 top
RD12  66.5_0402_1%  [R_0402]  200.23 8.42 180 top
RD13  66.5_0402_1%  [R_0402]  200.23 7.47 180 top
RD14  2M_0402_5%  [R_0402]  149.02 20.67 90 top
RD15  0_0402_5%  [R0402_0OHM]  139.24 15.28 0 top
RD16  0_0402_5%  [R0402_0OHM]  139.24 14.33 0 top
RD18  1.8K_0402_1%  [R_0402]  198.6 13.06 0 top
RD19  2_0402_1%  [R_0402]  200.44 13.06 0 top
RD20  1.8K_0402_1%  [R_0402]  200.48 12.17 180 top
RD21  24.9_0402_1%  [R_0402]  203.2 12.11 180 top
RD22  1.8K_0402_1%  [R_0402]  161.11 18.26 180 top
RD23  2_0402_1%  [R_0402]  159.2 18.26 180 top
RD24  1.8K_0402_1%  [R_0402]  160.2 17.31 0 top
RD25  24.9_0402_1%  [R_0402]  159.2 16.36 180 top
RD27  0_0402_5%  [R0402_0OHM]  222.67 17 0 top
RD28  0_0402_5%  [R0402_0OHM]  222.11 19.11 270 top
RE5  100K_0402_5%  [R_0402]  247.01 60.79 90 top
RE8  100K_0402_5%  [R_0402]  258.94 73.72 270 top
RE9  100K_0402_5%  [R_0402]  263.41 62.78 180 top
RE10  100K_0402_5%  [R_0402]  263.41 63.73 180 top
RE11  100K_0402_5%  [R_0402]  253.3 73.9 270 top
RE12  100K_0402_5%  [R_0402]  251.82 57.06 90 top
RE17  100K_0402_5%  [R_0402]  246.16 62.59 0 top
RE20  100K_0402_5%  [R_0402]  252.71 57.06 90 top
RE21  10K_0402_5%  [R_0402]  258.87 57.18 90 top
RE24  10K_0402_5%  [R_0402]  247.07 70.47 180 top
RE25  100K_0402_5%  [R_0402]  263.39 60.81 180 top
RE26  10_0402_5%  [R_0402]  263.39 59.86 180 top
RE27  33_0402_5%  [R_0402]  247.07 64.5 180 top
RE31  100K_0402_5%  [R_0402]  268.59 51.68 270 top
RE32  0_0402_5%  [R0402_0OHM]  269.55 51.68 270 top
RE33  10K_0402_5%  [R_0402]  267.7 50.77 90 top
RE35  10K_0402_5%  [R_0402]  254.25 73.9 270 top
RE36  100K_0402_5%  [R_0402]  257.79 53.21 270 top
RE37  2.2K_0402_5%  [R_0402]  267.78 40.37 180 top
RE42  10K_0402_5%  [R_0402]  266.8 48.94 0 top
RE43  2.2K_0402_5%  [R_0402]  267.78 41.26 180 top
RE48  10K_0402_5%  [R_0402]  250.42 42.97 0 top
RE51  10K_0402_5%  [R_0402]  248.97 44.02 90 top
RE55  100K_0402_5%  [R_0402]  250.42 42.02 0 top
RE56  10K_0402_5%  [R_0402]  256.52 32.67 90 top
RE57  1K_0402_5%  [R_0402]  270.1 43.16 0 top
RE58  100K_0402_5%  [R_0402]  269.16 43.17 270 top
RE60  43_0402_5%  [R_0402]  264.02 34.79 270 top
RE61  0_0402_5%  [R0402_0OHM]  266.81 46.73 270 top
RE62  100K_0402_5%  [R_0402]  267.71 49.83 180 top
RE63  100K_0402_5%  [R_0402]  264.08 31.24 270 top
RE64  4.7K_0402_5%  [R_0402]  270.1 42.21 0 top
RE65  100_0402_1%  [R_0402]  261.79 30.32 90 top
RE66  10_0402_5%  [R_0402]  251.33 38.97 180 top
RE67  10K_0402_5%  [R_0402]  250.16 49.38 0 top
RE68  100K_0402_5%  [R_0402]  248.46 48.44 270 top
RE69  8.2K_0402_5%  [R_0402]  250.43 36.99 0 top
RE70  2.2K_0402_5%  [R_0402]  251.79 32.8 180 top
RE71  49.9_0402_1%  [R_0402]  300.44 41.3 180 top
RE72  10K_0402_5%  [R_0402]  300.87 37.5 180 top
RE73  10K_0402_5%  [R_0402]  300.87 35.47 180 top
RE74  10K_0402_5%  [R_0402]  300.87 34.58 180 top
RE75  100K_0402_5%  [R_0402]  300.87 36.36 180 top
RE77  1.58K_0402_1%  [R_0402]  251.33 44.88 180 top
RE78  1K_0402_5%  [R_0402]  257.16 41.38 0 bottom
RE79  1K_0402_5%  [R_0402]  258.75 53.21 270 top
RE81  10K_0402_5%  [R_0402]  271.33 49.01 270 top
RE82  10K_0402_5%  [R_0402]  270.44 49.01 270 top
RE83  100K_0402_5%  [R_0402]  265.93 61.89 180 top
RE84  100K_0402_5%  [R_0402]  265.25 63.73 180 top
RE86  10K_0402_5%  [R_0402]  258.3 34.73 270 top
RE88  47K_0402_5%  [R_0402]  263.81 32.55 0 top
RE274  0_0402_5%  [R_0402]  238.94 36.8 0 top
RE275  0_0402_5%  [R0402_0OHM]  255.2 73.9 270 top
RE276  10K_0402_5%  [R_0402]  250.89 57.05 90 top
RE277  100K_0402_5%  [R_0402]  251.39 46.66 270 bottom
RE279  0_0402_5%  [R0402_0OHM]  256.3 31.29 270 top
RE280  0_0402_5%  [R_0402]  255.41 31.29 270 top
RE281  0_0402_5%  [R_0402]  253.58 30.28 0 top
RE282  0_0402_5%  [R0402_0OHM]  253.58 31.29 0 top
RE283  0_0402_5%  [R_0402]  267.01 32.02 90 top
RI13  10K_0402_5%  [R_0402]  288.66 39.03 0 top
RI14  22.1K_0402_1%  [R_0402]  284.53 42.16 270 top
RL1  10K_0402_5%  [R_0402]  262.2 87.1 180 top
RL2  10K_0402_5%  [R_0402]  262.2 88.62 180 top
RL3  0_0402_5%  [R0402_0OHM]  253.67 86.92 270 bottom
RL4  4.7K_0402_5%  [R_0402]  254.12 90.45 90 top
RL5  10K_0402_5%  [R_0402]  252.35 91.36 270 top
RL6  4.7K_0402_5%  [R_0402]  253.24 91.36 270 top
RL7  0_0402_5%  [R0402_0OHM]  249.54 90.46 0 top
RL8  0_0603_5%  [R0603_0OHM]  248.89 87.55 0 top
RL9  10K_0402_5%  [R_0402]  251.39 90.45 90 top
RL10  0_0402_5%  [R0402_0OHM]  248.78 84.62 0 top
RL11  1M_0402_5%  [R_0402]  250.63 84.19 270 top
RL12  1K_0402_5%  [R_0402]  261.27 85.58 0 top
RL13  3.01K_0402_1%  [R_0402]  251.52 80.5 270 top
RL14  150_0402_5%  [R_0402]  282.95 83.78 90 top
RL15  75_0402_1%  [R_0402]  267.99 90.18 90 top
RL16  75_0402_1%  [R_0402]  269.26 90.18 90 top
RL17  75_0402_1%  [R_0402]  275.61 90.18 90 top
RL18  75_0402_1%  [R_0402]  276.88 90.18 90 top
RL19  150_0402_5%  [R_0402]  283.84 83.78 90 top
RL20  150_0402_5%  [R_0402]  284.73 83.78 90 top
RL21  2.2_0603_5%  [R_0603]  252.59 80.44 270 top
RL22  2.2_0603_5%  [R_0603]  253.79 80.44 270 top
RL23  2.2_0603_5%  [R_0603]  255.06 80.44 270 top
RL24  2.2_0603_5%  [R_0603]  256.27 80.44 270 top
RL25  2.2_0603_5%  [R_0603]  257.54 80.44 270 top
RL26  2.2_0603_5%  [R_0603]  258.75 80.44 270 top
RL27  2.2_0603_5%  [R_0603]  260.02 80.44 270 top
RL28  2.2_0603_5%  [R_0603]  261.22 80.44 270 top
RL29  1M_0402_5%  [R_0402]  278.67 77.41 0 top
RL30  1M_0402_5%  [R_0402]  268.09 70.88 180 top
RN1  100K_0402_5%  [R_0402]  272.32 10.08 0 bottom
RN2  100K_0402_5%  [R_0402]  276.53 14.03 270 bottom
RN3  2.2K_0402_5%  [R_0402]  278.11 4.27 0 bottom
RN4  2.2K_0402_5%  [R_0402]  280.87 4.27 180 bottom
RN5  10K_0402_5%  [R_0402]  268.33 10.98 270 bottom
RN6  10K_0402_5%  [R_0402]  247.81 17.69 270 top
RN7  10K_0402_5%  [R_0402]  247.81 15.89 0 top
RN8  4.7K_0402_5%  [R_0402]  260.42 15.85 180 top
RN9  4.7K_0402_5%  [R_0402]  259.51 16.74 0 top
RN10  4.7K_0402_5%  [R_0402]  260.42 18.52 180 top
RN11  4.7K_0402_5%  [R_0402]  259.51 17.63 0 top
RN12  4.7K_0402_5%  [R_0402]  267.7 17.5 0 top
RN13  4.7K_0402_5%  [R_0402]  268.62 16.61 180 top
RN14  4.7K_0402_5%  [R_0402]  268.62 18.39 180 top
RN16  4.7K_0402_5%  [R_0402]  268.62 19.28 180 top
RN18  4.7K_0402_5%  [R_0402]  259.51 19.47 0 top
RN19  7.87K_0402_1%  [R_0402]  259.51 20.36 0 top
RN20  4.7K_0402_5%  [R_0402]  268.62 14.83 180 top
RN21  4.7K_0402_5%  [R_0402]  268.62 15.72 180 top
RN22  4.7K_0402_5%  [R_0402]  260.49 13.94 0 top
RN23  4.7K_0402_5%  [R_0402]  260.49 13.06 0 top
RN24  4.7K_0402_5%  [R_0402]  267.14 13.06 90 top
RN25  4.7K_0402_5%  [R_0402]  266.27 13.06 90 top
RPC1  10K_8P4R_5%  [RP_0804_8P4R]  176.16 44.67 90 top
RPC2  2.2K_0804_8P4R_5%  [RP_0804_8P4R]  164.85 83.72 180 bottom
RPC3  10K_8P4R_5%  [RP_0804_8P4R]  180.13 68.93 0 top
RPC4  10K_8P4R_5%  [RP_0804_8P4R]  177.93 67.23 180 top
RPC5  10K_8P4R_5%  [RP_0804_8P4R]  185.28 58.86 180 top
RPC6  10K_8P4R_5%  [RP_0804_8P4R]  179.94 64.26 0 bottom
RPC7  10K_8P4R_5%  [RP_0804_8P4R]  184.39 58.26 180 bottom
RPC8  10K_8P4R_5%  [RP_0804_8P4R]  179.88 67.05 0 bottom
RPC9  10K_8P4R_5%  [RP_0804_8P4R]  181.28 64.57 180 top
RPC10  10K_8P4R_5%  [RP_0804_8P4R]  185.28 55.94 180 top
RPC11  33_0804_8P4R_5%  [RP_0804_8P4R]  187.81 62.39 0 top
RPC12  33_0804_8P4R_5%  [RP_0804_8P4R]  187.81 56.23 0 top
RPC14  2.2K_0804_8P4R_5%  [RP_0804_8P4R]  183.18 60 0 bottom
RPC15  10K_8P4R_5%  [RP_0804_8P4R]  180.32 62.9 0 top
RPC16  10K_8P4R_5%  [RP_0804_8P4R]  184.15 67.55 180 top
RPC17  10K_8P4R_5%  [RP_0804_8P4R]  177.91 68.68 180 bottom
RPC18  10K_8P4R_5%  [RP_0804_8P4R]  177.91 65.88 180 bottom
RPC19  10K_8P4R_5%  [RP_0804_8P4R]  177.6 58.28 0 bottom
RPC20  100K_0804_8P4R_5%  [RP_0804_8P4R]  169.71 82.02 90 bottom
RPE2  100K_0804_8P4R_5%  [RP_0804_8P4R]  259.24 31.93 270 top
RPE3  2.2K_0804_8P4R_5%  [RP_0804_8P4R]  260.35 51.73 90 top
RPE4  100K_0804_8P4R_5%  [RP_0804_8P4R]  249.25 73.12 90 top
RPE5  100K_0804_8P4R_5%  [RP_0804_8P4R]  263.27 51.73 90 top
RPE6  10K_8P4R_5%  [RP_0804_8P4R]  262.73 34.15 270 top
RPE7  10K_8P4R_5%  [RP_0804_8P4R]  299.85 40.15 0 top
RPE8  100K_0804_8P4R_5%  [RP_0804_8P4R]  246.68 66.86 180 top
RPE9  100K_0804_8P4R_5%  [RP_0804_8P4R]  255.5 57.71 270 top
RPE10  100K_0804_8P4R_5%  [RP_0804_8P4R]  253.87 52.18 90 top
RPV1  2.2K_0804_8P4R_5%  [RP_0804_8P4R]  210.31 84.69 90 top
RPV2  2.2K_0804_8P4R_5%  [RP_0804_8P4R]  199.38 80.07 180 top
RR1  10_0402_5%  [R_0402]  283.89 35.97 90 top
RR2  191_0402_1%  [R_0402]  278.56 32.74 0 top
RR3  0_0402_5%  [R0402_0OHM]  282.75 35.97 90 top
RR4  0_0402_5%  [R0402_0OHM]  281.86 35.97 90 top
RR5  4.7K_0402_1%  [R_0402]  289.68 28.31 270 top
RR6  100K_0402_5%  [R_0402]  283.4 24.15 90 top
RR8  100K_0402_5%  [R_0402]  284.29 25.07 270 top
RR11  1M_0402_5%  [R_0402]  275.79 27.67 270 top
RR15  10K_0402_5%  [R_0402]  281.8 26.33 0 top
RV1  4.7K_0402_5%  [R_0402]  116.71 86.19 90 top
RV2  4.7K_0402_5%  [R_0402]  119.36 86.27 0 top
RV3  100K_0402_5%  [R_0402]  121.57 87.85 180 top
RV4  270K_0402_5%  [R_0402]  111.77 81.19 180 top
RV5  47K_0402_5%  [R_0402]  109.92 82.09 270 top
RV6  47K_0402_5%  [R_0402]  99.9 87.73 180 top
RV7  2.2K_0402_5%  [R_0402]  223.02 93.89 180 top
RV8  10K_0402_5%  [R_0402]  223.02 95.8 180 top
RV9  2.2K_0402_5%  [R_0402]  223.02 94.84 180 top
RV50  4.99K_0402_1%  [R_0402]  221.17 80.06 180 top
RV51  4.7K_0402_5%  [R_0402]  233.28 78.71 90 top
RV52  4.7K_0402_5%  [R_0402]  232.39 79.62 270 top
RV54  4.7K_0402_5%  [R_0402]  222.37 75.78 90 top
RV55  4.7K_0402_5%  [R_0402]  222.02 77.44 0 bottom
RV56  4.7K_0402_5%  [R_0402]  222.02 78.37 0 bottom
RV57  4.7K_0402_5%  [R_0402]  233.56 81.76 90 bottom
RV58  4.7K_0402_5%  [R_0402]  228.37 78.14 90 bottom
RV60  4.7K_0402_5%  [R_0402]  235.4 84 180 bottom
RV61  4.7K_0402_5%  [R_0402]  221.49 76.69 270 top
RV62  4.7K_0402_5%  [R_0402]  223.78 77.44 0 bottom
RV63  4.7K_0402_5%  [R_0402]  232.66 82.68 270 bottom
RV64  4.7K_0402_5%  [R_0402]  223.78 78.37 0 bottom
RV65  4.7K_0402_5%  [R_0402]  229.28 79.06 270 bottom
RV66  4.7K_0402_5%  [R_0402]  233.55 83.6 180 bottom
RV67  1M_0402_5%  [R_0402]  230.5 75.78 90 top
RV68  100K_0402_5%  [R_0402]  227.01 78.16 90 bottom
RV73  1M_0402_5%  [R_0402]  214.44 75.17 270 top
RV74  1M_0402_5%  [R_0402]  199.26 78.79 180 top
RV75  1M_0402_5%  [R_0402]  207.12 84.49 90 top
RV76  150_0402_1%  [R_0402]  213.78 77.83 0 top
RV77  150_0402_1%  [R_0402]  213.85 79.15 90 top
RV78  150_0402_1%  [R_0402]  213.85 81.85 270 top
RV79  100K_0402_5%  [R_0402]  200.39 69.27 270 top
RV80  1M_0402_5%  [R_0402]  213.34 71.34 90 top
RV81  1.8K_0402_1%  [R_0402]  215.59 71.67 180 top
RV82  1M_0402_5%  [R_0402]  208 84.5 0 top
RV83  2.2K_0402_5%  [R_0402]  202.17 69.27 270 top
RV84  1M_0402_5%  [R_0402]  201.28 69.27 270 top
RV85  1M_0402_5%  [R_0402]  199.26 77.9 180 top
RV86  10K_0402_5%  [R_0402]  197.85 73.32 0 top
RV87  2.2K_0402_5%  [R_0402]  193.93 72.44 270 bottom
RV88  10K_0402_5%  [R_0402]  215.39 75.17 270 top
RV89  3.74K_0402_1%  [R_0402]  213.78 76.94 0 top
RV90  100K_0402_5%  [R_0402]  211.97 87.22 180 top
RV91  100K_0402_5%  [R_0402]  197.88 82.97 180 top
RV100  4.7K_0402_5%  [R_0402]  231.63 76.25 0 top
RV210  100K_0402_5%  [R_0402]  200.75 64.71 180 bottom
RV212  100K_0402_5%  [R_0402]  198.97 62.97 180 bottom
RV501  100K_0402_5%  [R_0402]  281.92 71.6 0 top
RV502  100K_0402_5%  [R_0402]  281.92 72.55 0 top
RV503  5.1M_0402_5%  [R_0402]  286.24 75.41 0 top
RV504  1M_0402_5%  [R_0402]  285.63 71.35 180 top
RV505  100K_0402_5%  [R_0402]  288.68 70.46 180 top
